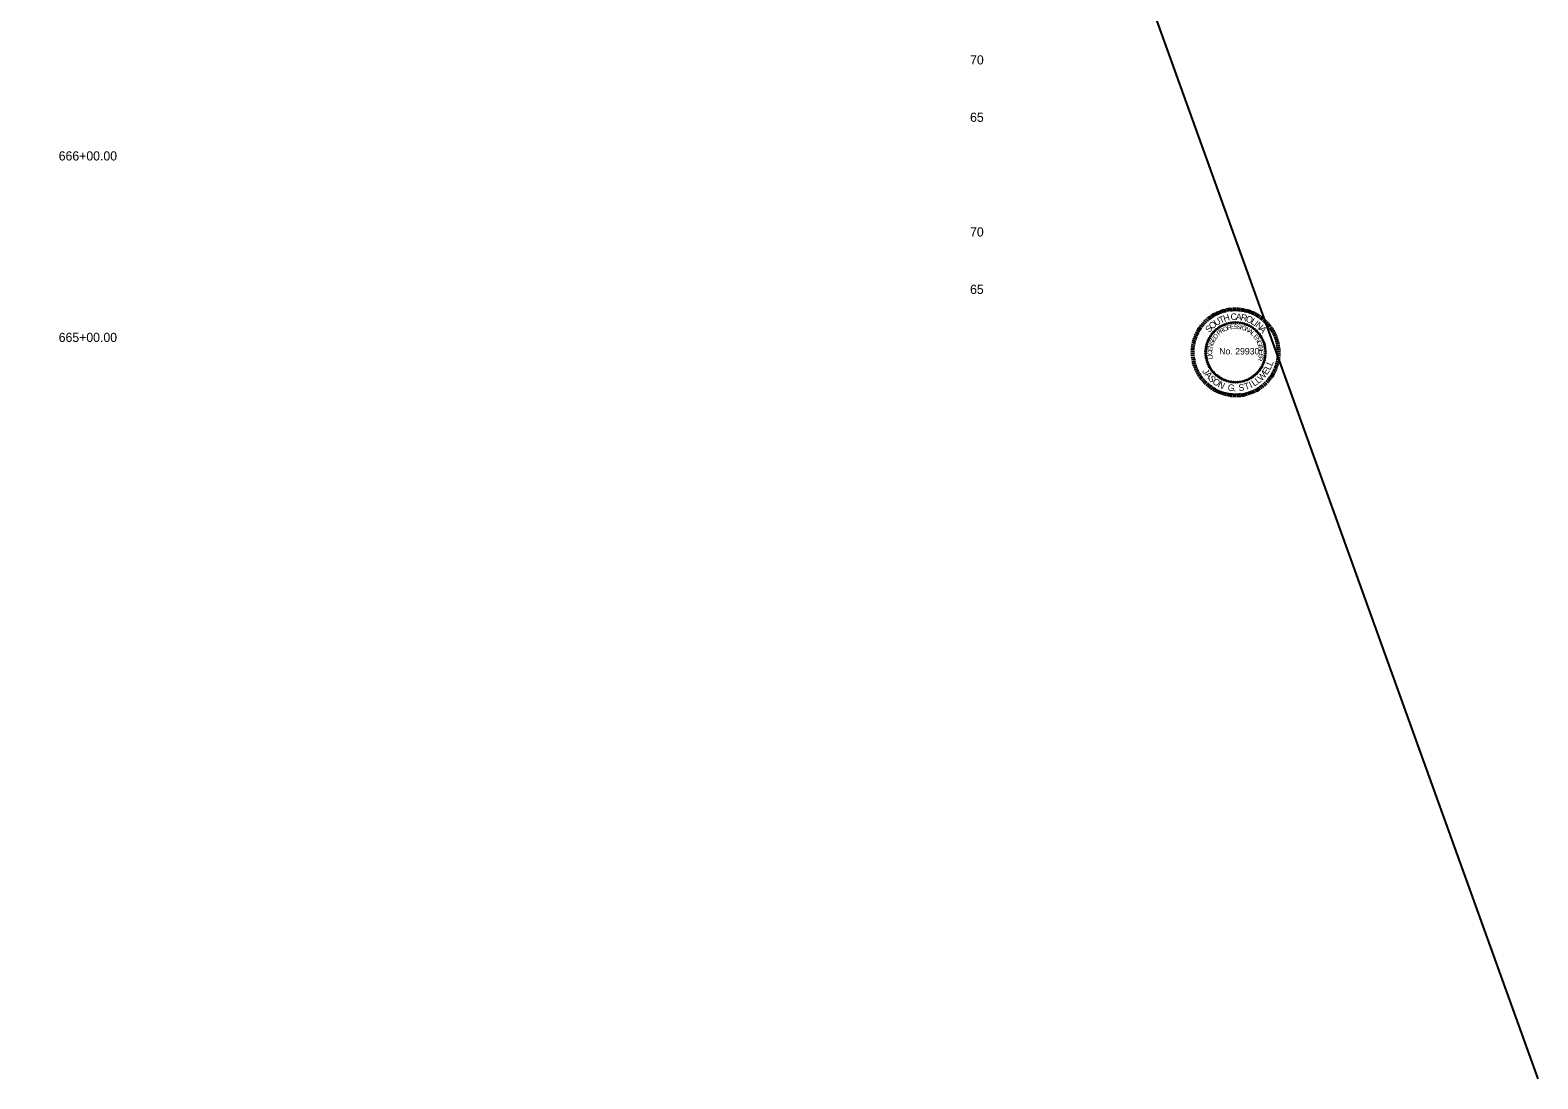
# Model space of a CAD drawing. Extents: x 952 to 1206, y 942 to 2399.
# Drawn here: x 1074.9 to 1206.4, y 941.6 to 1033 of the extents above; entities that cross this region are included whole.
import ezdxf

# ---------------------------------------------------------------- set-up
doc = ezdxf.new("R2010")
doc.units = 0
for name, color, linetype in [('Default', 7, 'Continuous'), ('RD_SHT_TX', 7, 'Continuous'), ('RD_TX_PEShield', 7, 'Continuous'), ('RD_XS_TX_Elev_EX', 7, 'Continuous'), ('RD_XS_TX_Station', 7, 'Continuous')]:
    doc.layers.add(name, color=color, linetype=linetype)

# ---------------------------------------------------------------- blocks, each defined once
blk = doc.blocks.new('STILLWELL')
at = {"layer": 'RD_TX_PEShield'}
for p, q in [((-25.1, 24.7), (-27.4, 27.1)), ((-23.8, 25.9), (-26, 28.4)), ((-22.5, 27), (-24.5, 29.6)), ((-21.1, 28.1), (-23, 30.7)), ((-19.7, 29.1), (-21.5, 31.8)), ((-18.2, 30), (-19.9, 32.8)), ((-16.7, 30.8), (-18.2, 33.7)), ((-15.1, 31.6), (-16.5, 34.6)), ((-13.6, 32.3), (-14.8, 35.3)), ((-11.9, 32.9), (-13, 36)), ((-10.3, 33.4), (-11.2, 36.6)), ((-8.6, 33.9), (-9.4, 37.1)), ((-6.9, 34.3), (-7.5, 37.5)), ((-5.2, 34.6), (-5.7, 37.8)), ((-3.5, 34.8), (-3.8, 38)), ((-1.8, 34.9), (-1.9, 38.2)), ((0, 34.9), (0, 38.2)), ((1.7, 34.9), (1.9, 38.2)), ((3.4, 34.8), (3.7, 38)), ((5.2, 34.6), (5.6, 37.8)), ((6.9, 34.3), (7.5, 37.5)), ((8.6, 33.9), (9.3, 37.1)), ((10.2, 33.4), (11.2, 36.6)), ((11.9, 32.9), (13, 36)), ((13.5, 32.3), (14.7, 35.3)), ((15.1, 31.6), (16.5, 34.6)), ((16.6, 30.8), (18.2, 33.7)), ((18.2, 30), (19.8, 32.8)), ((19.6, 29.1), (21.4, 31.8)), ((21.1, 28.1), (23, 30.7)), ((22.4, 27), (24.5, 29.6)), ((23.8, 25.9), (25.9, 28.4)), ((25, 24.7), (27.3, 27.1)), ((-32.9, 13.4), (-35.9, 14.7)), ((-32.2, 15), (-35.1, 16.4)), ((-31.4, 16.5), (-34.2, 18.1)), ((-30.5, 18), (-33.3, 19.7)), ((-29.5, 19.4), (-32.2, 21.3)), ((-28.5, 20.9), (-31.1, 22.8)), ((-27.4, 22.2), (-29.9, 24.3)), ((-26.3, 23.5), (-28.7, 25.7)), ((26.2, 23.5), (28.6, 25.7)), ((27.4, 22.2), (29.9, 24.3)), ((28.5, 20.9), (31.1, 22.8)), ((29.5, 19.4), (32.2, 21.3)), ((30.4, 18), (33.2, 19.7)), ((31.3, 16.5), (34.2, 18.1)), ((32.1, 15), (35.1, 16.4)), ((32.9, 13.4), (35.9, 14.7)), ((-35.9, -0.1), (-39.2, 0)), ((-35.8, 1.7), (-39.1, 1.9)), ((-35.6, 3.4), (-38.9, 3.8)), ((-35.4, 5.1), (-38.6, 5.7)), ((-35.1, 6.8), (-38.2, 7.5)), ((-34.6, 8.5), (-37.8, 9.4)), ((-34.1, 10.2), (-37.2, 11.2)), ((-33.6, 11.8), (-36.6, 12.9)), ((33.5, 11.8), (36.6, 12.9)), ((34.1, 10.2), (37.2, 11.2)), ((34.6, 8.5), (37.7, 9.4)), ((35, 6.8), (38.2, 7.5)), ((35.3, 5.1), (38.5, 5.7)), ((35.6, 3.4), (38.8, 3.8)), ((35.7, 1.7), (39, 1.9)), ((35.8, -0.1), (39.1, 0)), ((-35.9, -1.8), (-39.2, -1.9)), ((-35.8, -3.5), (-39.1, -3.8)), ((-35.6, -5.3), (-38.9, -5.6)), ((-35.4, -7), (-38.6, -7.5)), ((-35.1, -8.7), (-38.2, -9.4)), ((-34.6, -10.4), (-37.8, -11.2)), ((-34.1, -12), (-37.2, -13)), ((34.1, -12), (37.2, -13)), ((34.6, -10.4), (37.7, -11.2)), ((35, -8.7), (38.2, -9.4)), ((35.3, -7), (38.5, -7.5)), ((35.6, -5.3), (38.8, -5.6)), ((35.7, -3.5), (39, -3.8)), ((35.8, -1.8), (39.1, -1.9)), ((-33.6, -13.6), (-36.6, -14.8)), ((-32.9, -15.3), (-35.9, -16.6)), ((-32.2, -16.8), (-35.1, -18.3)), ((-31.4, -18.4), (-34.2, -19.9)), ((-30.5, -19.9), (-33.3, -21.6)), ((-29.5, -21.3), (-32.2, -23.2)), ((-28.5, -22.7), (-31.1, -24.7)), ((-27.4, -24.1), (-29.9, -26.2)), ((-26.3, -25.4), (-28.7, -27.6)), ((26.2, -25.4), (28.6, -27.6)), ((27.4, -24.1), (29.9, -26.2)), ((28.5, -22.7), (31.1, -24.7)), ((29.5, -21.3), (32.2, -23.2)), ((30.4, -19.9), (33.2, -21.6)), ((31.3, -18.4), (34.2, -19.9)), ((32.1, -16.8), (35.1, -18.3)), ((32.9, -15.3), (35.9, -16.6)), ((33.5, -13.6), (36.6, -14.8)), ((-25.1, -26.6), (-27.4, -28.9)), ((-23.8, -27.8), (-26, -30.2)), ((-22.5, -28.9), (-24.5, -31.4)), ((-21.1, -29.9), (-23, -32.6)), ((-19.7, -30.9), (-21.5, -33.7)), ((-18.2, -31.8), (-19.9, -34.7)), ((-16.7, -32.7), (-18.2, -35.6)), ((-15.1, -33.5), (-16.5, -36.4)), ((-13.6, -34.1), (-14.8, -37.2)), ((-11.9, -34.8), (-13, -37.8)), ((-10.3, -35.3), (-11.2, -38.4)), ((-8.6, -35.8), (-9.4, -38.9)), ((-6.9, -36.1), (-7.5, -39.3)), ((-5.2, -36.4), (-5.7, -39.7)), ((-3.5, -36.6), (-3.8, -39.9)), ((-1.8, -36.8), (-1.9, -40)), ((0, -36.8), (0, -40.1)), ((1.7, -36.8), (1.9, -40)), ((3.4, -36.6), (3.7, -39.9)), ((5.2, -36.4), (5.6, -39.7)), ((6.9, -36.1), (7.5, -39.3)), ((8.6, -35.8), (9.3, -38.9)), ((10.2, -35.3), (11.2, -38.4)), ((11.9, -34.8), (13, -37.8)), ((13.5, -34.1), (14.7, -37.2)), ((15.1, -33.5), (16.5, -36.4)), ((16.6, -32.7), (18.2, -35.6)), ((18.2, -31.8), (19.8, -34.7)), ((19.6, -30.9), (21.4, -33.7)), ((21.1, -29.9), (23, -32.6)), ((22.4, -28.9), (24.5, -31.4)), ((23.8, -27.8), (25.9, -30.2)), ((25, -26.6), (27.3, -28.9))]:
    blk.add_line(p, q, dxfattribs=at)
for centre in [(-21.9, 13.2), (-20.7, 14.9), (-19.5, 16.4), (-18.1, 17.8), (-16.6, 19.2), (-15, 20.4), (-13.3, 21.5), (-11.6, 22.4), (-9.8, 23.2), (-7.9, 23.9), (-6, 24.4), (-4, 24.8), (-2, 25), (0, 25.1), (2, 25), (3.9, 24.8), (5.9, 24.4), (7.8, 23.9), (9.7, 23.2), (11.5, 22.4), (13.3, 21.5), (15, 20.4), (16.5, 19.2), (18, 17.8), (19.4, 16.4), (20.7, 14.9), (21.8, 13.2), (-26.1, 0.1), (-25.9, 2.1), (-25.6, 4), (-25.1, 6), (-24.5, 7.9), (-23.8, 9.7), (-22.9, 11.5), (22.9, 11.5), (23.7, 9.7), (24.5, 7.9), (25.1, 6), (25.5, 4), (25.8, 2.1), (26, 0.1), (-26.1, -1.9), (-25.9, -3.9), (-25.6, -5.9), (-25.1, -7.8), (-24.5, -9.7), (-23.8, -11.6), (-22.9, -13.4), (22.9, -13.4), (23.7, -11.6), (24.5, -9.7), (25.1, -7.8), (25.5, -5.9), (25.8, -3.9), (26, -1.9), (-21.9, -15.1), (-20.7, -16.7), (-19.5, -18.3), (-18.1, -19.7), (-16.6, -21), (-15, -22.2), (-13.3, -23.3), (-11.6, -24.3), (-9.8, -25.1), (-7.9, -25.8), (-6, -26.3), (-4, -26.7), (3.9, -26.7), (5.9, -26.3), (7.8, -25.8), (9.7, -25.1), (11.5, -24.3), (13.3, -23.3), (15, -22.2), (16.5, -21), (18, -19.7), (19.4, -18.3), (20.7, -16.7), (21.8, -15.1), (-2, -26.9), (0, -27), (2, -26.9)]:
    blk.add_circle(centre, 0.49, dxfattribs=at)
for s, height, rotation, p in [('U', 5.68, 32.2152, (-16.9, 21.8)), ('T', 5.68, 23.5044, (-13.2, 24.1)), ('H', 5.68, 16.1357, (-9.9, 25.6)), ('C', 5.68, 4.076, (-4.2, 27.1)), ('A', 5.68, 355.3651, (0.1, 27.4)), ('R', 5.68, 347.3188, (4.1, 27.1)), ('O', 5.68, 338.6079, (8.3, 26.2)), ('L', 5.68, 329.226, (12.6, 24.4)), ('I', 5.68, 322.5218, (15.5, 22.8)), ('S', 5.68, 49.6435, (-22.9, 15.8)), ('O', 5.68, 41.5972, (-20.4, 18.8)), ('D', 3.92, 52.5376, (-17.1, 10.3)), ('P', 3.92, 41.0022, (-14.5, 13.5)), ('R', 3.92, 33.3057, (-12.5, 15.3)), ('O', 3.92, 24.9735, (-10, 16.9)), ('F', 3.92, 15.9995, (-7.1, 18.3)), ('E', 3.92, 8.9511, (-4.7, 19)), ('S', 3.92, 1.2546, (-1.9, 19.4)), ('S', 3.92, 353.558, (0.8, 19.5)), ('I', 3.92, 345.8615, (3.5, 19.2)), ('O', 3.92, 342.6583, (4.7, 19)), ('N', 3.92, 333.6842, (7.7, 18)), ('A', 3.92, 325.3521, (10.4, 16.7)), ('L', 3.92, 317.6555, (12.6, 15.1)), ('E', 3.92, 308.0396, (15.1, 12.8)), ('N', 5.68, 319.1729, (16.8, 21.8)), ('A', 5.68, 310.4621, (20.1, 19)), ('C', 3.92, 92.2915, (-20.4, -3.2)), ('E', 3.92, 83.9594, (-20.5, -0.2)), ('N', 3.92, 76.2628, (-20.2, 2.5)), ('S', 3.92, 67.9307, (-19.5, 5.4)), ('E', 3.92, 60.2341, (-18.5, 7.9)), ('N', 3.92, 300.343, (16.8, 10.6)), ('G', 3.92, 292.0109, (18.3, 8.1)), ('I', 3.92, 283.0368, (19.5, 5.1)), ('N', 3.92, 279.8336, (19.8, 4)), ('E', 3.92, 271.5014, (20.3, 1.1)), ('I', 3.92, 95.4947, (-20.2, -4.3)), ('L', 3.92, 101.9075, (-19.7, -6.6)), ('R', 3.92, 256.1083, (20.1, -4.4)), ('E', 3.92, 263.8049, (20.4, -1.7)), ('L', 5.68, 65.098, (30, -16.9)), ('L', 5.68, 65.098, (31.6, -13.3)), ('J', 5.68, 299.033, (-29.4, -17.3)), ('A', 5.68, 310.5887, (-27.2, -20.6)), ('S', 5.68, 310.5887, (-24.3, -24)), ('O', 5.68, 321.0072, (-20.8, -27.4)), ('N', 5.68, 333.4326, (-16, -30.8)), ('L', 5.68, 34.0644, (16.2, -30.9)), ('L', 5.68, 37.6708, (19.6, -28.7)), ('W', 5.68, 47.0518, (22.6, -26.4)), ('E', 5.68, 56.4327, (27.3, -21.1)), ('G', 5.68, 352.2045, (-7.2, -34.2)), ('.', 5.68, 0.8698, (-1.8, -34.9)), ('S', 5.68, 8.0826, (2.9, -34.8)), ('T', 5.68, 18.9019, (8.5, -33.9)), ('I', 5.68, 25.3991, (13.3, -32.2))]:
    blk.add_text(s, height=height, rotation=rotation, dxfattribs=at).set_placement(p)
blk.add_text('No. 29930', height=5.68, dxfattribs=at).set_placement((-14.3, -2.8))

msp = doc.modelspace()

# ---------------------------------------------------------------- linework, layer by layer
at = {"layer": 'RD_SHT_TX'}
msp.add_line((980.77, 1567.94), (1206.44, 941.58), dxfattribs=at)

# ---------------------------------------------------------------- block references
at = {"layer": 'Default', "xscale": 0.1, "yscale": 0.10000000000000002}
msp.add_blockref('STILLWELL', (1180.08, 1005), dxfattribs=at)

# ---------------------------------------------------------------- texts
at = {"layer": 'RD_XS_TX_Elev_EX'}
for s, p in [('70', (1156.92, 1030)), ('65', (1156.92, 1025)), ('70', (1156.92, 1015)), ('65', (1156.92, 1010))]:
    msp.add_text(s, height=0.8, dxfattribs=at).set_placement(p)
at = {"layer": 'RD_XS_TX_Station'}
for s, p in [('666+00.00', (1077.44, 1021.63)), ('665+00.00', (1077.44, 1005.81))]:
    msp.add_text(s, height=0.8, dxfattribs=at).set_placement(p)

doc.saveas('drawing.dxf')
